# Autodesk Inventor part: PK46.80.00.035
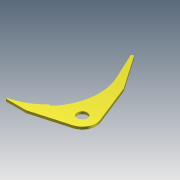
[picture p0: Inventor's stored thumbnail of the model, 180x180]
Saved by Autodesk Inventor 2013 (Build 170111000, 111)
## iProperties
Shininess: 64.0
Length Units: 11269
Angle Units: 11279
Time Units: 11290
Mass Units: 11283
Length Display Precision: 3
Angle Display Precision: 2
Compacted: True
Part Number: PK46.80.00.035
Document SubType Name: Modeling
Created: 2005-01
Material: Steel, Mild
Designer: SAlex
Manufacturer: Standard
Standards Organization: Custom
Density: 7.86 g/cm^3
Mass: 17355.9 g
Surface Area: 2723.6 cm^2
Volume: 2208.13 cm^3
Density: 0.0
Volumn: 0.0
Area: 0.0
PropertySet Name: Model Information
Control State: 0
Master: False
Checked Out: False
Checked Out Date: 2008-10-15
Last Check In Date: 2008-10-15
Author: SAlex
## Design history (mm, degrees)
sketch "Sketch1"
  geometry: L1 (-420, -188)-(-260, -188); L2 (-260, -188)-(29.987, -105.834); L3 (-20, 350)-(102.306, 40.417); L4 (-20, 350)-(-206.915, 620.625); L5 (-206.915, 620.625)-(-225.041, 612.172); L6 (-225.041, 612.172)-(-125.725, 399.19); L7 (-420, -177.95)-(-420, -188); L8 (-510, 220)-(-125.725, 399.19); L9 (-211.37, -58)-(-189.856, -58); C1 r 40 at (0, 0); A1 r 110 centre (0, 0) between (29.987, -105.834) and (102.306, 40.417); A2 r 408 centre (-510, 220) between (-420, -177.95) and (-211.37, -58); A3 r 424 centre (-510, 220) between (-189.856, -58) and (-125.725, 399.19)
  constraints: 18 end point, 6 point on circle, 4 centre point, 3 perpendicular, 3 tangent, 1 coincident, 1 horizontal, 1 other
  dimensions: "d0" = 80 diameter of C1; "d1" = 110 radius of A1; "d3" = 188 distance from line of L1 A1.centre; "d25" = 510 horizontal distance of L8.start C1.centre; "d26" = 220 vertical distance of L8.start C1.centre; "d29" = 90 distance from line of L7 L8.start; "d30" = 160 distance of L1.start L1.end; "d31" = 235 distance of L5.end L6.end; "d32" = 130 vertical distance of L3.start L8.start; "d33" = 490 horizontal distance of L3.start L8.start; "d35" = 115 deg angle of L7 L8; "d36" = 20 distance of L4.end L5.end; "d38" = 408 radius of A2; "d39" = 424 radius of A3; "d40" = 130 distance between parallel lines of L9 L1
extrude "Extrusion1" new body sketch "Sketch1" distance "d10" = 20; taper "d11" = 0 deg
body "Solid1"
other parameters: "d28" = 408
